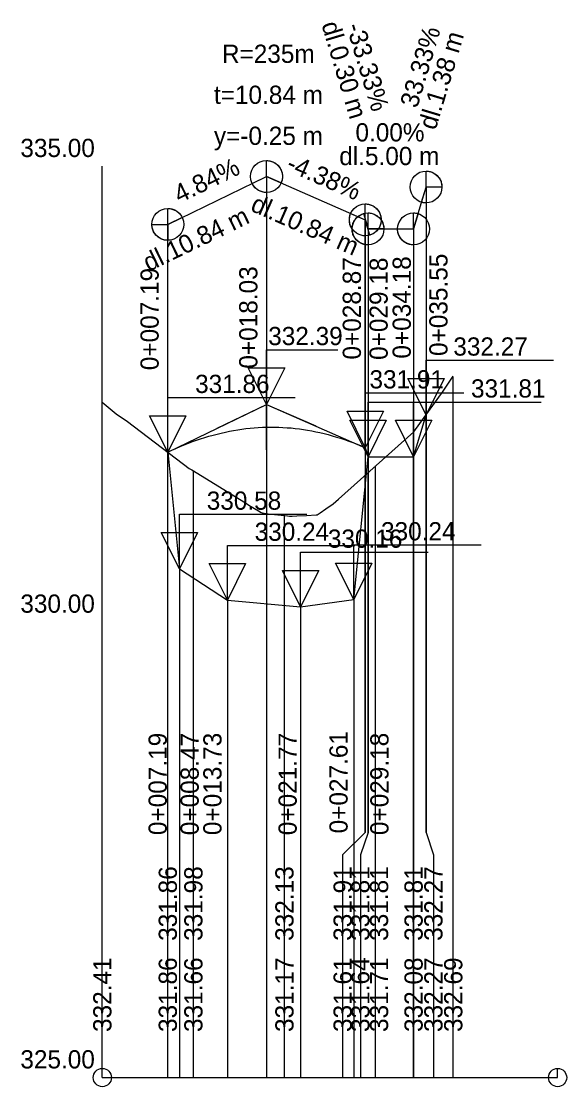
# Model space of a CAD drawing. Extents: x -559854 to -559644, y -1163827 to -1163530.
# Drawn here: x -559774.9 to -559715, y -1163707.4 to -1163590.5 of the extents above; entities that cross this region are included whole.
import ezdxf

# ---------------------------------------------------------------- set-up
doc = ezdxf.new("R2010")
doc.units = 0
for name, color, linetype in [('13', 7, 'Continuous'), ('14', 7, 'Continuous'), ('16', 7, 'Continuous'), ('46', 7, 'Continuous'), ('56', 7, 'Continuous'), ('8', 7, 'Continuous')]:
    doc.layers.add(name, color=color, linetype=linetype)

msp = doc.modelspace()

# ---------------------------------------------------------------- linework, layer by layer
for p, q in [((-559727.5, -1163706.43), (-559727.5, -1163629.53)), ((-559766.04, -1163706.43), (-559766.04, -1163632.33)), ((-559753.43, -1163635.19), (-559748.01, -1163632.57)), ((-559748.01, -1163637.57), (-559748.01, -1163632.57)), ((-559748.01, -1163632.57), (-559742.59, -1163634.94)), ((-559731.86, -1163638.32), (-559730.49, -1163633.72)), ((-559730.49, -1163679.53), (-559730.49, -1163633.73)), ((-559731.86, -1163706.43), (-559731.86, -1163635.63)), ((-559737.17, -1163637.32), (-559737.16, -1163637.32)), ((-559737.17, -1163637.32), (-559737.16, -1163637.32)), ((-559737.16, -1163637.32), (-559736.86, -1163638.32)), ((-559758.85, -1163637.82), (-559758.85, -1163637.82)), ((-559758.85, -1163637.82), (-559757.57, -1163650.63)), ((-559758.85, -1163637.82), (-559758.85, -1163637.82)), ((-559758.85, -1163706.43), (-559758.85, -1163637.83)), ((-559758.85, -1163706.43), (-559758.85, -1163637.83)), ((-559738.43, -1163653.99), (-559736.86, -1163638.32)), ((-559736.86, -1163638.32), (-559731.86, -1163638.32)), ((-559736.04, -1163706.43), (-559736.04, -1163639.33)), ((-559756.04, -1163706.43), (-559756.04, -1163639.83)), ((-559737.16, -1163679.53), (-559737.16, -1163640.33)), ((-559736.86, -1163679.53), (-559736.86, -1163640.03)), ((-559746.04, -1163706.43), (-559746.04, -1163644.73)), ((-559757.57, -1163650.63), (-559752.31, -1163654.04)), ((-559752.31, -1163654.04), (-559744.27, -1163654.8)), ((-559744.27, -1163654.8), (-559738.43, -1163653.99))]:
    msp.add_line(p, q)
for points in [[(-559766.04, -1163632.33), (-559764.52, -1163633.62), (-559763.28, -1163634.45), (-559756.49, -1163639.62), (-559756.2, -1163639.76), (-559750.3, -1163643.39), (-559749.94, -1163643.61), (-559748.88, -1163644.24), (-559748.58, -1163644.42), (-559748.49, -1163644.48), (-559747.83, -1163644.58), (-559746.78, -1163644.7), (-559745.72, -1163644.8), (-559745.5, -1163644.82), (-559745.37, -1163644.82), (-559745.36, -1163644.82), (-559745.19, -1163644.82), (-559744.67, -1163644.81), (-559743.61, -1163644.77), (-559742.56, -1163644.69), (-559742.46, -1163644.68), (-559742.12, -1163644.46), (-559741.5, -1163644.04), (-559740.68, -1163643.47), (-559740.12, -1163642.96), (-559731.82, -1163635.58), (-559728.6, -1163631.11), (-559727.5, -1163629.49)], [(-559758.85, -1163637.82), (-559758.4, -1163637.6), (-559757.95, -1163637.4), (-559757.49, -1163637.2), (-559757.04, -1163637.01), (-559756.59, -1163636.83), (-559756.14, -1163636.66), (-559755.69, -1163636.5), (-559755.24, -1163636.35), (-559754.78, -1163636.2), (-559754.33, -1163636.07), (-559753.88, -1163635.94), (-559753.43, -1163635.82), (-559752.98, -1163635.71), (-559752.53, -1163635.61), (-559752.07, -1163635.51), (-559751.62, -1163635.43), (-559751.17, -1163635.35), (-559750.72, -1163635.29), (-559750.27, -1163635.23), (-559749.82, -1163635.18), (-559749.36, -1163635.14), (-559748.91, -1163635.11), (-559748.46, -1163635.08), (-559747.56, -1163635.06), (-559747.11, -1163635.07), (-559746.65, -1163635.08), (-559746.2, -1163635.1), (-559745.75, -1163635.13), (-559745.3, -1163635.16), (-559744.85, -1163635.21), (-559744.4, -1163635.26), (-559743.94, -1163635.33), (-559743.49, -1163635.4), (-559743.04, -1163635.48), (-559742.59, -1163635.57), (-559742.14, -1163635.67), (-559741.69, -1163635.77), (-559741.23, -1163635.89), (-559740.78, -1163636.01), (-559740.33, -1163636.15), (-559739.88, -1163636.29), (-559739.43, -1163636.44), (-559738.98, -1163636.6), (-559738.52, -1163636.76), (-559738.07, -1163636.94), (-559737.62, -1163637.13), (-559737.17, -1163637.32)], [(-559758.85, -1163637.82), (-559758.4, -1163637.6), (-559757.95, -1163637.4), (-559757.49, -1163637.2), (-559757.04, -1163637.01), (-559756.59, -1163636.83), (-559756.14, -1163636.66), (-559755.69, -1163636.5), (-559755.24, -1163636.35), (-559754.78, -1163636.2), (-559754.33, -1163636.07), (-559753.88, -1163635.94), (-559753.43, -1163635.82), (-559752.98, -1163635.71), (-559752.53, -1163635.61), (-559752.07, -1163635.51), (-559751.62, -1163635.43), (-559751.17, -1163635.35), (-559750.72, -1163635.29), (-559750.27, -1163635.23), (-559749.82, -1163635.18), (-559749.36, -1163635.14), (-559748.91, -1163635.11), (-559748.46, -1163635.08), (-559747.56, -1163635.06), (-559747.11, -1163635.07), (-559746.65, -1163635.08), (-559746.2, -1163635.1), (-559745.75, -1163635.13), (-559745.3, -1163635.16), (-559744.85, -1163635.21), (-559744.4, -1163635.26), (-559743.94, -1163635.33), (-559743.49, -1163635.4), (-559743.04, -1163635.48), (-559742.59, -1163635.57), (-559742.14, -1163635.67), (-559741.69, -1163635.77), (-559741.23, -1163635.89), (-559740.78, -1163636.01), (-559740.33, -1163636.15), (-559739.88, -1163636.29), (-559739.43, -1163636.44), (-559738.98, -1163636.6), (-559738.52, -1163636.76), (-559738.07, -1163636.94), (-559737.62, -1163637.13), (-559737.17, -1163637.32)], [(-559739.65, -1163681.99), (-559737.17, -1163679.53), (-559737.17, -1163640.33)]]:
    msp.add_lwpolyline(points)
for centre in [(-559766.04, -1163706.43), (-559716.04, -1163706.43)]:
    msp.add_circle(centre, 1)
at = {"layer": '14'}
for p, q in [((-559758.85, -1163612.82), (-559748.01, -1163607.57)), ((-559748.01, -1163607.57), (-559748.01, -1163706.43)), ((-559748.01, -1163607.57), (-559737.16, -1163612.32)), ((-559731.86, -1163613.32), (-559730.49, -1163608.72)), ((-559730.49, -1163608.72), (-559730.49, -1163679.53)), ((-559737.16, -1163612.32), (-559737.16, -1163679.53)), ((-559737.16, -1163612.32), (-559736.86, -1163613.32)), ((-559758.85, -1163612.82), (-559758.85, -1163612.82)), ((-559736.86, -1163613.32), (-559736.86, -1163679.53)), ((-559736.86, -1163613.32), (-559731.86, -1163613.32)), ((-559731.86, -1163613.32), (-559731.86, -1163706.43)), ((-559758.85, -1163637.82), (-559748.01, -1163632.57)), ((-559748.01, -1163632.57), (-559748.01, -1163706.43)), ((-559748.01, -1163632.57), (-559737.16, -1163637.32)), ((-559731.86, -1163638.32), (-559730.49, -1163633.72)), ((-559731.86, -1163638.32), (-559730.49, -1163633.72)), ((-559731.86, -1163638.32), (-559730.49, -1163633.72)), ((-559737.17, -1163637.32), (-559737.16, -1163637.32)), ((-559737.17, -1163637.32), (-559737.16, -1163637.32)), ((-559737.16, -1163637.32), (-559736.86, -1163638.32)), ((-559737.16, -1163637.32), (-559736.86, -1163638.32)), ((-559737.16, -1163637.32), (-559737.16, -1163679.53)), ((-559737.16, -1163637.32), (-559736.86, -1163638.32)), ((-559758.85, -1163637.82), (-559757.57, -1163650.63)), ((-559758.85, -1163637.82), (-559758.85, -1163637.82)), ((-559758.85, -1163637.82), (-559758.85, -1163637.82)), ((-559758.85, -1163637.82), (-559758.85, -1163637.82)), ((-559758.85, -1163637.82), (-559757.57, -1163650.63)), ((-559758.85, -1163637.82), (-559758.85, -1163637.82)), ((-559758.85, -1163637.82), (-559757.57, -1163650.63)), ((-559738.43, -1163653.99), (-559736.86, -1163638.32)), ((-559738.43, -1163653.99), (-559736.86, -1163638.32)), ((-559738.43, -1163653.99), (-559736.86, -1163638.32)), ((-559736.86, -1163638.32), (-559731.86, -1163638.32)), ((-559736.86, -1163638.32), (-559731.86, -1163638.32)), ((-559736.86, -1163638.32), (-559736.86, -1163679.53)), ((-559736.86, -1163638.32), (-559731.86, -1163638.32)), ((-559731.86, -1163638.32), (-559731.86, -1163706.43)), ((-559757.57, -1163650.63), (-559752.31, -1163654.04)), ((-559757.57, -1163650.63), (-559757.57, -1163706.43)), ((-559757.57, -1163650.63), (-559752.31, -1163654.04)), ((-559752.31, -1163654.04), (-559744.27, -1163654.8)), ((-559752.31, -1163654.04), (-559752.31, -1163706.43)), ((-559752.31, -1163654.04), (-559744.27, -1163654.8)), ((-559744.27, -1163654.8), (-559738.43, -1163653.99)), ((-559744.27, -1163654.8), (-559738.43, -1163653.99)), ((-559744.27, -1163654.8), (-559744.27, -1163706.43)), ((-559738.43, -1163653.99), (-559738.43, -1163706.43)), ((-559739.65, -1163681.99), (-559739.65, -1163706.43)), ((-559737.7, -1163681.99), (-559737.7, -1163706.43)), ((-559729.68, -1163681.99), (-559729.68, -1163706.43))]:
    msp.add_line(p, q, dxfattribs=at)
for points in [[(-559730.49, -1163633.72), (-559730.49, -1163679.53), (-559729.68, -1163681.99)], [(-559758.85, -1163637.82), (-559758.4, -1163637.6), (-559757.95, -1163637.4), (-559757.49, -1163637.2), (-559757.04, -1163637.01), (-559756.59, -1163636.83), (-559756.14, -1163636.66), (-559755.69, -1163636.5), (-559755.24, -1163636.35), (-559754.78, -1163636.2), (-559754.33, -1163636.07), (-559753.88, -1163635.94), (-559753.43, -1163635.82), (-559752.98, -1163635.71), (-559752.53, -1163635.61), (-559752.07, -1163635.51), (-559751.62, -1163635.43), (-559751.17, -1163635.35), (-559750.72, -1163635.29), (-559750.27, -1163635.23), (-559749.82, -1163635.18), (-559749.36, -1163635.14), (-559748.91, -1163635.11), (-559748.46, -1163635.08), (-559747.56, -1163635.06), (-559747.11, -1163635.07), (-559746.65, -1163635.08), (-559746.2, -1163635.1), (-559745.75, -1163635.13), (-559745.3, -1163635.16), (-559744.85, -1163635.21), (-559744.4, -1163635.26), (-559743.94, -1163635.33), (-559743.49, -1163635.4), (-559743.04, -1163635.48), (-559742.59, -1163635.57), (-559742.14, -1163635.67), (-559741.69, -1163635.77), (-559741.23, -1163635.89), (-559740.78, -1163636.01), (-559740.33, -1163636.15), (-559739.88, -1163636.29), (-559739.43, -1163636.44), (-559738.98, -1163636.6), (-559738.52, -1163636.76), (-559738.07, -1163636.94), (-559737.62, -1163637.13), (-559737.17, -1163637.32)], [(-559736.86, -1163638.32), (-559736.86, -1163679.53), (-559737.7, -1163681.99)]]:
    msp.add_lwpolyline(points, dxfattribs=at)
at = {"layer": '16'}
msp.add_lwpolyline([(-559758.85, -1163637.82), (-559758.4, -1163637.6), (-559757.95, -1163637.4), (-559757.49, -1163637.2), (-559757.04, -1163637.01), (-559756.59, -1163636.83), (-559756.14, -1163636.66), (-559755.69, -1163636.5), (-559755.24, -1163636.35), (-559754.78, -1163636.2), (-559754.33, -1163636.07), (-559753.88, -1163635.94), (-559753.43, -1163635.82), (-559752.98, -1163635.71), (-559752.53, -1163635.61), (-559752.07, -1163635.51), (-559751.62, -1163635.43), (-559751.17, -1163635.35), (-559750.72, -1163635.29), (-559750.27, -1163635.23), (-559749.82, -1163635.18), (-559749.36, -1163635.14), (-559748.91, -1163635.11), (-559748.46, -1163635.08), (-559747.56, -1163635.06), (-559747.11, -1163635.07), (-559746.65, -1163635.08), (-559746.2, -1163635.1), (-559745.75, -1163635.13), (-559745.3, -1163635.16), (-559744.85, -1163635.21), (-559744.4, -1163635.26), (-559743.94, -1163635.33), (-559743.49, -1163635.4), (-559743.04, -1163635.48), (-559742.59, -1163635.57), (-559742.14, -1163635.67), (-559741.69, -1163635.77), (-559741.23, -1163635.89), (-559740.78, -1163636.01), (-559740.33, -1163636.15), (-559739.88, -1163636.29), (-559739.43, -1163636.44), (-559738.98, -1163636.6), (-559738.52, -1163636.76), (-559738.07, -1163636.94), (-559737.62, -1163637.13), (-559737.17, -1163637.32)], dxfattribs=at)
at = {"layer": '46'}
for points in [[(-559748.01, -1163607.57), (-559748.01, -1163605.82), (-559747.9, -1163605.82), (-559747.79, -1163605.83), (-559747.67, -1163605.85), (-559747.57, -1163605.88), (-559747.46, -1163605.91), (-559747.35, -1163605.95), (-559747.25, -1163605.99), (-559747.15, -1163606.04), (-559747.05, -1163606.1), (-559746.96, -1163606.17), (-559746.87, -1163606.24), (-559746.79, -1163606.31), (-559746.71, -1163606.39), (-559746.64, -1163606.48), (-559746.57, -1163606.57), (-559746.51, -1163606.66), (-559746.46, -1163606.76), (-559746.41, -1163606.86), (-559746.37, -1163606.97), (-559746.33, -1163607.07), (-559746.3, -1163607.18), (-559746.28, -1163607.29), (-559746.27, -1163607.4), (-559746.26, -1163607.51), (-559746.26, -1163607.63), (-559746.27, -1163607.74), (-559746.28, -1163607.85), (-559746.3, -1163607.96), (-559746.33, -1163608.07), (-559746.37, -1163608.17), (-559746.41, -1163608.27), (-559748.01, -1163607.57), (-559748.01, -1163609.32), (-559748.12, -1163609.32), (-559748.23, -1163609.31), (-559748.34, -1163609.29), (-559748.45, -1163609.26), (-559748.56, -1163609.23), (-559748.67, -1163609.19), (-559748.77, -1163609.15), (-559748.87, -1163609.09), (-559748.96, -1163609.04), (-559749.06, -1163608.97), (-559749.14, -1163608.9), (-559749.23, -1163608.83), (-559749.3, -1163608.75), (-559749.38, -1163608.66), (-559749.44, -1163608.57), (-559749.51, -1163608.48), (-559749.56, -1163608.38), (-559749.58, -1163608.33)], [(-559730.49, -1163608.72), (-559730.49, -1163606.97), (-559730.37, -1163606.98), (-559730.26, -1163606.99), (-559730.15, -1163607.01), (-559730.04, -1163607.03), (-559729.93, -1163607.06), (-559729.83, -1163607.1), (-559729.73, -1163607.15), (-559729.63, -1163607.2), (-559729.53, -1163607.26), (-559729.44, -1163607.32), (-559729.35, -1163607.39), (-559729.27, -1163607.47), (-559729.19, -1163607.55), (-559729.12, -1163607.63), (-559729.05, -1163607.72), (-559728.99, -1163607.82), (-559728.93, -1163607.91), (-559728.89, -1163608.02), (-559728.84, -1163608.12), (-559728.81, -1163608.23), (-559728.78, -1163608.33), (-559728.76, -1163608.44), (-559728.74, -1163608.56), (-559728.74, -1163608.67), (-559728.74, -1163608.72), (-559730.49, -1163608.72), (-559730.49, -1163610.47), (-559730.6, -1163610.47), (-559730.71, -1163610.46), (-559730.82, -1163610.44), (-559730.93, -1163610.42), (-559730.99, -1163610.4)], [(-559758.85, -1163612.82), (-559758.85, -1163611.07), (-559758.74, -1163611.07), (-559758.63, -1163611.09), (-559758.52, -1163611.1), (-559758.41, -1163611.13), (-559758.3, -1163611.16), (-559758.2, -1163611.2), (-559758.09, -1163611.24), (-559758, -1163611.3), (-559757.9, -1163611.35), (-559757.81, -1163611.42), (-559757.72, -1163611.49), (-559757.64, -1163611.56), (-559757.56, -1163611.64), (-559757.49, -1163611.73), (-559757.42, -1163611.82), (-559757.36, -1163611.91), (-559757.3, -1163612.01), (-559757.28, -1163612.06), (-559758.85, -1163612.82), (-559758.85, -1163614.57), (-559758.97, -1163614.57), (-559759.08, -1163614.56), (-559759.19, -1163614.54), (-559759.3, -1163614.51), (-559759.41, -1163614.48), (-559759.51, -1163614.44), (-559759.61, -1163614.4), (-559759.71, -1163614.35), (-559759.81, -1163614.29), (-559759.9, -1163614.22), (-559759.99, -1163614.15), (-559760.07, -1163614.08), (-559760.15, -1163614), (-559760.22, -1163613.91), (-559760.29, -1163613.82), (-559760.35, -1163613.73), (-559760.41, -1163613.63), (-559760.45, -1163613.53), (-559760.5, -1163613.43), (-559760.53, -1163613.32), (-559760.56, -1163613.21), (-559760.58, -1163613.1), (-559760.6, -1163612.99), (-559760.6, -1163612.88), (-559760.6, -1163612.82)], [(-559737.16, -1163612.32), (-559737.16, -1163610.57), (-559737.05, -1163610.57), (-559736.94, -1163610.59), (-559736.83, -1163610.6), (-559736.72, -1163610.63), (-559736.61, -1163610.66), (-559736.51, -1163610.7), (-559736.41, -1163610.74), (-559736.31, -1163610.8), (-559736.21, -1163610.85), (-559736.12, -1163610.92), (-559736.03, -1163610.99), (-559735.95, -1163611.06), (-559735.87, -1163611.14), (-559735.8, -1163611.23), (-559735.73, -1163611.32), (-559735.67, -1163611.41), (-559735.61, -1163611.51), (-559735.56, -1163611.61), (-559735.52, -1163611.72), (-559735.49, -1163611.82), (-559735.46, -1163611.93), (-559735.44, -1163612.04), (-559735.42, -1163612.15), (-559735.42, -1163612.27), (-559735.42, -1163612.38), (-559735.42, -1163612.49), (-559735.44, -1163612.6), (-559735.46, -1163612.71), (-559735.49, -1163612.82), (-559735.52, -1163612.93), (-559735.56, -1163613.03), (-559735.61, -1163613.13), (-559735.67, -1163613.23), (-559735.73, -1163613.32), (-559735.8, -1163613.41), (-559735.87, -1163613.5), (-559735.95, -1163613.58), (-559736.03, -1163613.65), (-559736.12, -1163613.72), (-559736.21, -1163613.79), (-559736.31, -1163613.85), (-559736.41, -1163613.9), (-559736.51, -1163613.94), (-559736.61, -1163613.98), (-559736.66, -1163614), (-559737.16, -1163612.32), (-559737.16, -1163614.07), (-559737.28, -1163614.07), (-559737.39, -1163614.06), (-559737.5, -1163614.04), (-559737.61, -1163614.01), (-559737.72, -1163613.98), (-559737.82, -1163613.94), (-559737.92, -1163613.9), (-559738.02, -1163613.85), (-559738.12, -1163613.79), (-559738.21, -1163613.72), (-559738.3, -1163613.65), (-559738.38, -1163613.58), (-559738.46, -1163613.5), (-559738.53, -1163613.41), (-559738.6, -1163613.32), (-559738.66, -1163613.23), (-559738.72, -1163613.13), (-559738.76, -1163613.03), (-559738.81, -1163612.93), (-559738.84, -1163612.82), (-559738.87, -1163612.71), (-559738.89, -1163612.6), (-559738.91, -1163612.49), (-559738.91, -1163612.38), (-559738.91, -1163612.27), (-559738.91, -1163612.15), (-559738.89, -1163612.04), (-559738.87, -1163611.93), (-559738.84, -1163611.82), (-559738.81, -1163611.72), (-559738.77, -1163611.62)], [(-559736.86, -1163613.32), (-559736.86, -1163611.57), (-559736.75, -1163611.57), (-559736.64, -1163611.59), (-559736.53, -1163611.6), (-559736.42, -1163611.63), (-559736.31, -1163611.66), (-559736.21, -1163611.7), (-559736.11, -1163611.74), (-559736.01, -1163611.8), (-559735.91, -1163611.85), (-559735.82, -1163611.92), (-559735.73, -1163611.99), (-559735.65, -1163612.06), (-559735.57, -1163612.14), (-559735.5, -1163612.23), (-559735.43, -1163612.32), (-559735.37, -1163612.41), (-559735.31, -1163612.51), (-559735.26, -1163612.61), (-559735.22, -1163612.72), (-559735.19, -1163612.82), (-559735.16, -1163612.93), (-559735.14, -1163613.04), (-559735.12, -1163613.15), (-559735.12, -1163613.27), (-559735.11, -1163613.32), (-559736.86, -1163613.32), (-559736.86, -1163615.07), (-559736.98, -1163615.07), (-559737.09, -1163615.06), (-559737.2, -1163615.04), (-559737.31, -1163615.01), (-559737.42, -1163614.98), (-559737.52, -1163614.94), (-559737.62, -1163614.9), (-559737.72, -1163614.85), (-559737.82, -1163614.79), (-559737.91, -1163614.72), (-559738, -1163614.65), (-559738.08, -1163614.58), (-559738.16, -1163614.5), (-559738.23, -1163614.41), (-559738.3, -1163614.32), (-559738.36, -1163614.23), (-559738.42, -1163614.13), (-559738.46, -1163614.03), (-559738.51, -1163613.93), (-559738.54, -1163613.82), (-559738.57, -1163613.71), (-559738.59, -1163613.6), (-559738.61, -1163613.49), (-559738.61, -1163613.38), (-559738.61, -1163613.27), (-559738.61, -1163613.15), (-559738.59, -1163613.04), (-559738.57, -1163612.93), (-559738.54, -1163612.82), (-559738.51, -1163612.72), (-559738.46, -1163612.61), (-559738.42, -1163612.51), (-559738.36, -1163612.41), (-559738.3, -1163612.32), (-559738.23, -1163612.23), (-559738.16, -1163612.14), (-559738.08, -1163612.06), (-559738, -1163611.99), (-559737.91, -1163611.92), (-559737.82, -1163611.85), (-559737.72, -1163611.8), (-559737.62, -1163611.74), (-559737.52, -1163611.7), (-559737.42, -1163611.66), (-559737.37, -1163611.64)], [(-559731.86, -1163613.32), (-559731.86, -1163611.57), (-559731.75, -1163611.57), (-559731.64, -1163611.59), (-559731.53, -1163611.6), (-559731.42, -1163611.63), (-559731.36, -1163611.64), (-559731.86, -1163613.32), (-559731.86, -1163615.07), (-559731.98, -1163615.07), (-559732.09, -1163615.06), (-559732.2, -1163615.04), (-559732.31, -1163615.01), (-559732.42, -1163614.98), (-559732.52, -1163614.94), (-559732.62, -1163614.9), (-559732.72, -1163614.85), (-559732.82, -1163614.79), (-559732.91, -1163614.72), (-559733, -1163614.65), (-559733.08, -1163614.58), (-559733.16, -1163614.5), (-559733.23, -1163614.41), (-559733.3, -1163614.32), (-559733.36, -1163614.23), (-559733.42, -1163614.13), (-559733.46, -1163614.03), (-559733.51, -1163613.93), (-559733.54, -1163613.82), (-559733.57, -1163613.71), (-559733.59, -1163613.6), (-559733.61, -1163613.49), (-559733.61, -1163613.38), (-559733.61, -1163613.32)], [(-559748.01, -1163632.57), (-559750.01, -1163628.57), (-559746.01, -1163628.57)], [(-559730.49, -1163633.72), (-559732.49, -1163629.72), (-559728.49, -1163629.72)], [(-559758.85, -1163637.82), (-559760.85, -1163633.82), (-559756.85, -1163633.82)], [(-559758.85, -1163637.82), (-559760.85, -1163633.82), (-559756.85, -1163633.82)], [(-559737.16, -1163637.32), (-559739.16, -1163633.32), (-559735.16, -1163633.32)], [(-559736.86, -1163638.32), (-559738.86, -1163634.32), (-559734.86, -1163634.32)], [(-559736.86, -1163638.32), (-559738.86, -1163634.32), (-559734.86, -1163634.32)], [(-559731.86, -1163638.32), (-559733.86, -1163634.32), (-559729.86, -1163634.32)], [(-559757.57, -1163650.63), (-559759.57, -1163646.63), (-559755.57, -1163646.63)], [(-559752.31, -1163654.04), (-559754.31, -1163650.04), (-559750.31, -1163650.04)], [(-559738.43, -1163653.99), (-559740.43, -1163649.99), (-559736.43, -1163649.99)], [(-559744.27, -1163654.8), (-559746.27, -1163650.8), (-559742.27, -1163650.8)]]:
    msp.add_lwpolyline(points, close=True, dxfattribs=at)
for centre in [(-559748.01, -1163607.57), (-559730.49, -1163608.72), (-559758.85, -1163612.82), (-559737.16, -1163612.32), (-559736.86, -1163613.32), (-559731.86, -1163613.32)]:
    msp.add_circle(centre, 1.75, dxfattribs=at)
at = {"layer": '56'}
for p, q in [((-559766.04, -1163706.43), (-559766.04, -1163606.43)), ((-559766.04, -1163706.43), (-559766.04, -1163705.43)), ((-559716.04, -1163706.43), (-559716.04, -1163705.43)), ((-559766.04, -1163706.43), (-559716.04, -1163706.43))]:
    msp.add_line(p, q, dxfattribs=at)
at = {"layer": '8'}
for p, q in [((-559737.17, -1163637.32), (-559737.17, -1163612.32)), ((-559758.85, -1163637.82), (-559758.85, -1163612.82)), ((-559748.01, -1163632.57), (-559748.01, -1163626.57)), ((-559748.01, -1163626.57), (-559740.19, -1163626.57)), ((-559730.49, -1163633.72), (-559730.49, -1163627.72)), ((-559730.49, -1163627.72), (-559716.49, -1163627.72)), ((-559737.16, -1163637.32), (-559737.16, -1163631.32)), ((-559737.16, -1163631.32), (-559726.33, -1163631.32)), ((-559758.85, -1163637.82), (-559758.85, -1163631.82)), ((-559758.85, -1163631.82), (-559744.85, -1163631.82)), ((-559758.85, -1163637.82), (-559758.85, -1163631.82)), ((-559758.85, -1163631.82), (-559744.85, -1163631.82)), ((-559736.86, -1163638.32), (-559736.86, -1163632.32)), ((-559736.86, -1163632.32), (-559722.86, -1163632.32)), ((-559736.86, -1163638.32), (-559736.86, -1163632.32)), ((-559736.86, -1163632.32), (-559722.86, -1163632.32)), ((-559731.86, -1163638.32), (-559731.86, -1163632.32)), ((-559731.86, -1163632.32), (-559717.86, -1163632.32)), ((-559757.57, -1163650.63), (-559757.57, -1163644.63)), ((-559757.57, -1163644.63), (-559743.57, -1163644.63)), ((-559752.31, -1163654.04), (-559752.31, -1163648.04)), ((-559752.31, -1163648.04), (-559738.31, -1163648.04)), ((-559744.27, -1163654.8), (-559744.27, -1163648.8)), ((-559744.27, -1163648.8), (-559730.27, -1163648.8)), ((-559738.43, -1163653.99), (-559738.43, -1163647.99)), ((-559738.43, -1163647.99), (-559724.43, -1163647.99))]:
    msp.add_line(p, q, dxfattribs=at)

# ---------------------------------------------------------------- texts
for s, p in [('331.86', (-559757.85, -1163691.43)), ('331.86', (-559757.85, -1163691.43)), ('331.98', (-559755.04, -1163691.43)), ('332.13', (-559745.04, -1163691.43)), ('331.91', (-559738.65, -1163691.43)), ('331.81', (-559736.7, -1163691.43)), ('331.81', (-559734.65, -1163691.43)), ('331.81', (-559730.86, -1163691.43)), ('332.27', (-559728.68, -1163691.43)), ('332.41', (-559765.04, -1163701.43)), ('331.86', (-559757.85, -1163701.43)), ('331.86', (-559757.85, -1163701.43)), ('331.66', (-559755.04, -1163701.43)), ('331.17', (-559745.04, -1163701.43)), ('331.61', (-559738.65, -1163701.43)), ('331.64', (-559736.7, -1163701.43)), ('331.71', (-559734.65, -1163701.43)), ('332.08', (-559730.86, -1163701.43)), ('332.27', (-559728.68, -1163701.43)), ('332.69', (-559726.5, -1163701.43))]:
    msp.add_text(s, height=2, rotation=90).set_placement(p)
at = {"layer": '13'}
for s, p in [('335.00', (-559775.04, -1163605.43)), ('335.00', (-559775.04, -1163605.43)), ('330.00', (-559775.04, -1163655.43)), ('325.00', (-559775.04, -1163705.43))]:
    msp.add_text(s, height=2, dxfattribs=at).set_placement(p)
at = {"layer": '16'}
for s, rotation, p in [('dl.0.30 m', 286.6992, (-559741.99, -1163590.88)), ('-33.33%', 286.6992, (-559739.28, -1163591.04)), ('33.33%', 73.3008, (-559731.47, -1163600.16)), ('dl.1.38 m', 73.3008, (-559729.45, -1163602.56)), ('4.84%', 25.8374, (-559757.57, -1163610.53)), ('-4.38%', 336.3408, (-559745.96, -1163606.83)), ('dl.10.84 m', 336.3408, (-559749.88, -1163611.28)), ('dl.10.84 m', 25.8374, (-559760.95, -1163618.04)), ('0+035.55', 90, (-559728.13, -1163627.26)), ('0+028.87', 90, (-559737.64, -1163627.65)), ('0+029.18', 90, (-559734.7, -1163627.69)), ('0+034.18', 90, (-559732.16, -1163627.55)), ('0+007.19', 90, (-559759.85, -1163628.82)), ('0+018.03', 90, (-559749.01, -1163628.65)), ('0+007.19', 90, (-559758.96, -1163679.83)), ('0+008.47', 90, (-559755.45, -1163679.84)), ('0+013.73', 90, (-559752.95, -1163679.83)), ('0+021.77', 90, (-559744.69, -1163679.84)), ('0+027.61', 90, (-559739.1, -1163679.64)), ('0+029.18', 90, (-559734.61, -1163679.83))]:
    msp.add_text(s, height=2, rotation=rotation, dxfattribs=at).set_placement(p)
for s, p in [('R=235m', (-559752.9, -1163595.1)), ('t=10.84 m', (-559753.78, -1163599.6)), ('y=-0.25 m', (-559753.78, -1163604.1)), ('0.00%', (-559738.24, -1163603.72)), ('dl.5.00 m', (-559740.02, -1163606.32)), ('332.39', (-559747.82, -1163626.07)), ('332.27', (-559727.49, -1163627.22)), ('331.91', (-559736.7, -1163630.82)), ('331.86', (-559755.85, -1163631.32)), ('331.86', (-559755.85, -1163631.32)), ('331.81', (-559725.55, -1163631.82)), ('330.58', (-559754.57, -1163644.13)), ('330.24', (-559749.31, -1163647.54)), ('330.24', (-559735.43, -1163647.49)), ('330.16', (-559741.27, -1163648.3))]:
    msp.add_text(s, height=2, dxfattribs=at).set_placement(p)

doc.saveas('drawing.dxf')
